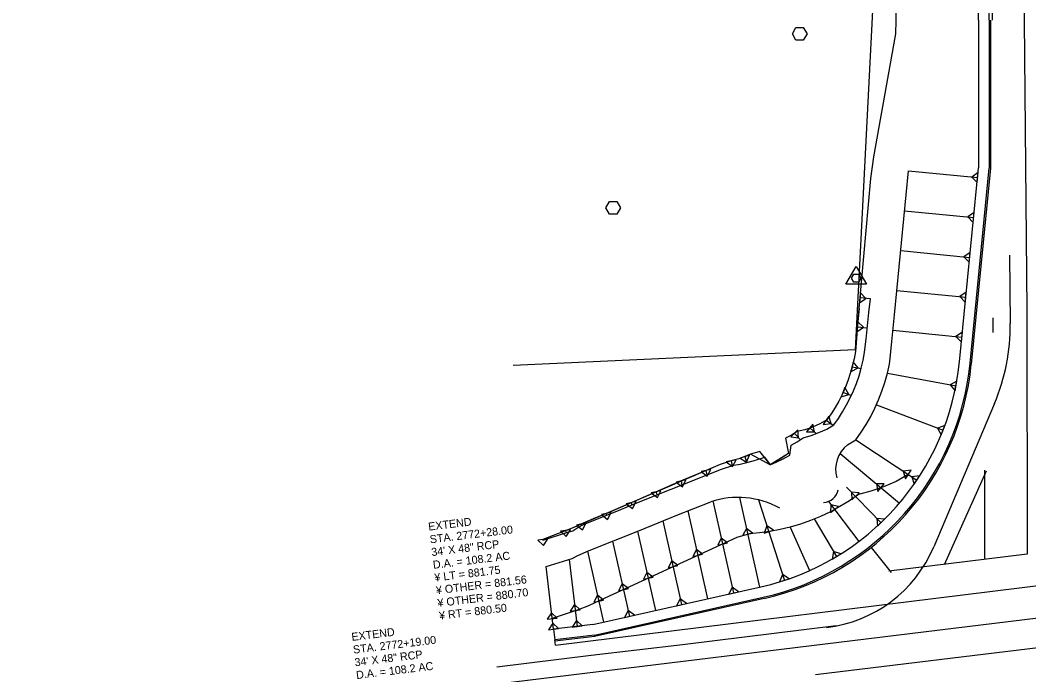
# Model space of a CAD drawing. Extents: x 18436148 to 18440034, y 7649939 to 7652226.
# Drawn here: x 18437956.9 to 18438334.9, y 7650259.9 to 7650505.1 of the extents above; entities that cross this region are included whole.
import ezdxf

# ---------------------------------------------------------------- set-up
doc = ezdxf.new("R2010")
doc.units = 0
for name, color, linetype in [('ATVEHICLE', 7, 'Continuous'), ('Drainage', 7, 'Continuous'), ('ROWTitleBlock', 7, 'Continuous'), ('Seeding', 7, 'Continuous'), ('TC_PCCPavement', 7, 'Continuous'), ('TC_Subbase', 7, 'Continuous'), ('TL_DitchFront', 7, 'Continuous'), ('TL_ShoulderBtm', 7, 'Continuous'), ('TSDETAILS', 7, 'Continuous'), ('TSOUTLINE', 7, 'Continuous')]:
    doc.layers.add(name, color=color, linetype=linetype)

msp = doc.modelspace()

# ---------------------------------------------------------------- linework, layer by layer
at = {"layer": 'ATVEHICLE'}
for p, q in [((18438320.05, 7650505.03), (18438320.13, 7650449.63)), ((18438312.93, 7650376.67), (18438320.13, 7650449.63)), ((18438157.51, 7650270.99), (18438464.57, 7650308.82)), ((18438172.17, 7650274.74), (18438235.33, 7650288.92)), ((18438403.52, 7650277.97), (18438255.05, 7650259.88)), ((18438172.17, 7650274.74), (18438157.28, 7650272.98)), ((18438157.51, 7650270.99), (18438157.28, 7650272.98))]:
    msp.add_line(p, q, dxfattribs=at)
for centre, radius, start, end in [((18431834.06, 7650496.24), 6486, 0.077652, 3.256258), ((18438213.41, 7650386.49), 100, 282.6576, 354.3671)]:
    msp.add_arc(centre, radius, start, end, dxfattribs=at)
at = {"layer": 'Drainage'}
for p, q in [((18438246.31, 7650499.94), (18438247.68, 7650502.32)), ((18438247.68, 7650502.32), (18438250.43, 7650502.32)), ((18438250.43, 7650502.32), (18438251.81, 7650499.94)), ((18438247.68, 7650497.56), (18438246.31, 7650499.94)), ((18438251.81, 7650499.94), (18438250.43, 7650497.56)), ((18438250.43, 7650497.56), (18438247.68, 7650497.56)), ((18438176.4, 7650434.84), (18438177.77, 7650437.22)), ((18438177.77, 7650432.46), (18438176.4, 7650434.84)), ((18438177.77, 7650437.22), (18438180.52, 7650437.22)), ((18438180.52, 7650437.22), (18438181.9, 7650434.84)), ((18438181.9, 7650434.84), (18438180.52, 7650432.46)), ((18438180.52, 7650432.46), (18438177.77, 7650432.46))]:
    msp.add_line(p, q, dxfattribs=at)
at = {"layer": 'Seeding'}
for p, q in [((18438266.31, 7650406.17), (18438270.18, 7650412.88)), ((18438270.18, 7650412.88), (18438274.06, 7650406.17)), ((18438268.43, 7650408.41), (18438269.31, 7650409.93)), ((18438269.31, 7650406.89), (18438268.43, 7650408.41)), ((18438269.31, 7650409.93), (18438271.06, 7650409.93)), ((18438271.06, 7650409.93), (18438271.93, 7650408.41)), ((18438271.93, 7650408.41), (18438271.06, 7650406.89)), ((18438274.06, 7650406.17), (18438266.31, 7650406.17)), ((18438271.06, 7650406.89), (18438269.31, 7650406.89))]:
    msp.add_line(p, q, dxfattribs=at)
at = {"layer": 'TC_PCCPavement'}
for p, q in [((18438282.29, 7650624.06), (18438269.8, 7650381.63)), ((18438269.8, 7650381.63), (18438141.66, 7650375.79))]:
    msp.add_line(p, q, dxfattribs=at)
at = {"layer": 'TC_Subbase'}
for p, q in [((18438289.86, 7650448.66), (18438315.78, 7650446.11)), ((18438288.4, 7650433.73), (18438314.31, 7650431.18)), ((18438286.93, 7650418.8), (18438312.83, 7650416.25)), ((18438285.47, 7650403.88), (18438311.36, 7650401.32)), ((18438275.54, 7650400.67), (18438271.66, 7650401.06)), ((18438270.73, 7650390.26), (18438274.38, 7650389.9)), ((18438284.01, 7650388.95), (18438309.89, 7650386.39)), ((18438268.74, 7650375.28), (18438272.12, 7650374.66)), ((18438281.97, 7650372.85), (18438307.65, 7650368.12)), ((18438265.45, 7650365.64), (18438268.44, 7650364.51)), ((18438277.79, 7650360.96), (18438302.8, 7650351.48)), ((18438258.95, 7650355.23), (18438261.65, 7650353.44)), ((18438252.84, 7650352.34), (18438255.4, 7650350.19)), ((18438247.07, 7650350.31), (18438249.38, 7650347.93)), ((18438270.08, 7650347.89), (18438292.99, 7650332.79)), ((18438223.38, 7650340.04), (18438223.81, 7650338.15)), ((18438228.51, 7650341.64), (18438229.17, 7650339.56)), ((18438264.21, 7650342.81), (18438286.43, 7650324.2)), ((18438213.95, 7650336.42), (18438214.32, 7650334.78)), ((18438204.6, 7650332.45), (18438204.91, 7650331.04)), ((18438195.25, 7650328.43), (18438195.51, 7650327.27)), ((18438266.66, 7650330.13), (18438279.52, 7650316.88)), ((18438185.92, 7650324.35), (18438186.11, 7650323.5)), ((18438216.52, 7650325.01), (18438224.31, 7650290.54)), ((18438226.47, 7650326.35), (18438234.06, 7650292.74)), ((18438233.69, 7650325.41), (18438243.31, 7650295.26)), ((18438259.87, 7650324.82), (18438271.19, 7650309.82)), ((18438176.58, 7650320.29), (18438176.72, 7650319.71)), ((18438207.12, 7650321.26), (18438214.55, 7650288.35)), ((18438197.72, 7650317.5), (18438204.79, 7650286.16)), ((18438254.55, 7650318.26), (18438262.84, 7650304.19)), ((18438161.33, 7650313.93), (18438161.4, 7650313.27)), ((18438167.22, 7650316.38), (18438167.33, 7650315.86)), ((18438188.32, 7650313.73), (18438195.04, 7650283.97)), ((18438245.44, 7650315.19), (18438252.79, 7650298.94)), ((18438178.92, 7650309.94), (18438185.28, 7650281.78)), ((18438169.53, 7650306.15), (18438175.52, 7650279.59)), ((18438162.63, 7650303.05), (18438165.63, 7650277.99)), ((18438156.81, 7650276.95), (18438154.03, 7650300.41))]:
    msp.add_line(p, q, dxfattribs=at)
for points in [[(18438267.01, 7650346.03), (18438270.08, 7650347.89), (18438272.1, 7650350.74), (18438273.96, 7650353.64), (18438275.67, 7650356.63), (18438277.24, 7650359.72), (18438278.65, 7650362.89), (18438279.91, 7650366.13), (18438281.02, 7650369.43), (18438281.97, 7650372.85), (18438282.66, 7650376.23), (18438283.08, 7650379.62), (18438283.58, 7650384.71), (18438284.08, 7650389.69), (18438284.56, 7650394.66), (18438289.86, 7650448.66)], [(18438240.48, 7650339.61), (18438242.92, 7650340.82), (18438245.31, 7650342.16), (18438245.85, 7650345.85), (18438248.18, 7650347.14), (18438250.41, 7650348.61), (18438253.35, 7650349.49), (18438256.28, 7650350.59), (18438259.19, 7650351.9), (18438261.84, 7650353.56), (18438263.56, 7650355.94), (18438265.17, 7650358.41), (18438266.65, 7650360.96), (18438268.02, 7650363.59), (18438269.25, 7650366.29), (18438270.35, 7650369.05), (18438271.32, 7650371.88), (18438272.15, 7650374.76), (18438272.84, 7650377.68), (18438273.37, 7650380.57), (18438273.38, 7650380.69), (18438273.92, 7650385.66), (18438274.46, 7650390.63), (18438274.99, 7650395.61), (18438275.54, 7650400.67)], [(18438271.3, 7650397.13), (18438270.77, 7650391), (18438270.35, 7650386.02), (18438269.93, 7650381.03), (18438269.92, 7650380.92), (18438269.42, 7650378.19), (18438268.78, 7650375.43), (18438268, 7650372.72), (18438267.11, 7650370.05), (18438266.09, 7650367.43), (18438264.95, 7650364.87), (18438263.68, 7650362.38), (18438262.3, 7650359.97), (18438260.8, 7650357.63), (18438259.18, 7650355.37), (18438256.63, 7650353.83), (18438253.81, 7650352.66), (18438250.97, 7650351.7), (18438248.12, 7650350.96), (18438245.99, 7650349.62), (18438243.77, 7650348.46), (18438244.81, 7650342.84), (18438242.61, 7650341.3), (18438240.32, 7650339.89), (18438237.96, 7650338.61), (18438234.15, 7650343.58), (18438230.64, 7650342.54), (18438228.46, 7650341.62), (18438226.23, 7650340.83), (18438223.81, 7650340.19), (18438219.3, 7650338.7), (18438214.62, 7650336.71), (18438205.27, 7650332.73), (18438200.59, 7650330.74), (18438195.92, 7650328.72), (18438191.25, 7650326.7), (18438181.92, 7650322.59), (18438177.25, 7650320.57), (18438172.57, 7650318.62), (18438167.88, 7650316.68), (18438163.84, 7650314.83), (18438152.83, 7650310.58)], [(18438152.86, 7650310.34), (18438162.57, 7650313.38), (18438164.04, 7650313.84), (18438165.9, 7650315.07), (18438167.99, 7650316.17), (18438172.69, 7650318.07), (18438177.39, 7650319.96), (18438182.09, 7650321.86), (18438186.79, 7650323.75), (18438191.49, 7650325.64), (18438196.19, 7650327.52), (18438200.89, 7650329.4), (18438205.59, 7650331.28), (18438210.3, 7650333.16), (18438215, 7650335.03), (18438219.71, 7650336.9), (18438224.36, 7650338.36), (18438226.8, 7650338.8), (18438229.22, 7650339.38), (18438231.6, 7650340.09), (18438234.94, 7650341.07), (18438235.85, 7650341.36), (18438237.99, 7650338.53), (18438240.48, 7650339.61)], [(18438289.76, 7650334.92), (18438285.22, 7650332.23), (18438280.5, 7650330.31), (18438275.77, 7650328.73), (18438271.06, 7650327.47), (18438267.71, 7650325.04), (18438264.17, 7650322.9), (18438260.56, 7650320.96), (18438256.88, 7650319.22), (18438253.14, 7650317.68), (18438249.37, 7650316.35), (18438245.55, 7650315.22), (18438241.72, 7650314.29), (18438237.87, 7650313.57), (18438234.03, 7650313.05), (18438230.25, 7650312.75), (18438225.46, 7650311.3), (18438174.36, 7650287.8), (18438169.89, 7650285.7), (18438166.02, 7650284.21), (18438156.34, 7650280.92)], [(18438154.03, 7650300.41), (18438163.75, 7650303.39), (18438165.97, 7650304.59), (18438170.18, 7650306.41), (18438188.98, 7650313.99), (18438203.08, 7650319.65), (18438215.74, 7650324.7)]]:
    msp.add_lwpolyline(points, dxfattribs=at)
for points in [[(18438313.52, 7650446.33), (18438315.57, 7650444.24), (18438315.95, 7650447.97)], [(18438312.05, 7650431.41), (18438314.1, 7650429.31), (18438314.48, 7650433.04)], [(18438310.58, 7650416.48), (18438312.62, 7650414.38), (18438313.01, 7650418.11)], [(18438273.9, 7650400.83), (18438271.84, 7650402.92), (18438271.47, 7650399.19)], [(18438309.09, 7650401.55), (18438311.13, 7650399.46), (18438311.51, 7650403.19)], [(18438272.95, 7650390.04), (18438270.89, 7650392.13), (18438270.53, 7650388.39)], [(18438307.63, 7650386.61), (18438309.69, 7650384.53), (18438310.05, 7650388.26)], [(18438270.95, 7650374.87), (18438269.08, 7650377.12), (18438268.4, 7650373.44)], [(18438305.42, 7650368.49), (18438307.29, 7650366.23), (18438307.97, 7650369.92)], [(18438267.42, 7650364.89), (18438265.98, 7650367.45), (18438264.65, 7650363.94)], [(18438260.83, 7650353.99), (18438259.98, 7650356.79), (18438257.92, 7650353.66)], [(18438248.65, 7650348.69), (18438248.42, 7650351.61), (18438245.73, 7650349)], [(18438254.57, 7650350.89), (18438254.05, 7650353.77), (18438251.64, 7650350.9)], [(18438300.7, 7650352.28), (18438302.14, 7650349.73), (18438303.47, 7650353.23)], [(18438223.88, 7650337.85), (18438225.21, 7650340.46), (18438221.55, 7650339.63)], [(18438229.19, 7650339.5), (18438230.3, 7650342.21), (18438226.72, 7650341.07)], [(18438214.44, 7650334.23), (18438215.77, 7650336.84), (18438212.12, 7650336.01)], [(18438287.89, 7650336.16), (18438288.73, 7650333.35), (18438290.8, 7650336.49)], [(18438205.09, 7650330.25), (18438206.42, 7650332.86), (18438202.77, 7650332.03)], [(18438291.11, 7650334.03), (18438291.96, 7650331.23), (18438294.02, 7650334.36)], [(18438195.75, 7650326.24), (18438197.08, 7650328.84), (18438193.42, 7650328.02)], [(18438268.43, 7650328.31), (18438268.64, 7650325.39), (18438271.34, 7650328)], [(18438277.8, 7650331.43), (18438278.32, 7650328.55), (18438280.73, 7650331.42)], [(18438186.41, 7650322.16), (18438187.75, 7650324.76), (18438184.09, 7650323.94)], [(18438177.08, 7650318.1), (18438178.41, 7650320.7), (18438174.76, 7650319.88)], [(18438260.79, 7650323.61), (18438260.65, 7650320.68), (18438263.64, 7650322.94)], [(18438167.71, 7650314.19), (18438169.04, 7650316.79), (18438165.39, 7650315.97)], [(18438277.96, 7650318.49), (18438278.18, 7650315.57), (18438280.87, 7650318.18)], [(18438161.59, 7650311.7), (18438163.19, 7650314.15), (18438159.46, 7650313.71)], [(18438229.09, 7650314.74), (18438227.76, 7650312.14), (18438231.42, 7650312.96)], [(18438236.8, 7650315.66), (18438235.7, 7650312.95), (18438239.27, 7650314.09)], [(18438153.1, 7650308.34), (18438154.69, 7650310.8), (18438150.97, 7650310.35)], [(18438219.67, 7650311.07), (18438218.33, 7650308.47), (18438221.99, 7650309.29)], [(18438210.38, 7650306.82), (18438209.05, 7650304.21), (18438212.7, 7650305.03)], [(18438261.7, 7650306.13), (18438261.22, 7650303.24), (18438264.45, 7650305.14)], [(18438201.09, 7650302.56), (18438199.76, 7650299.95), (18438203.41, 7650300.77)], [(18438191.81, 7650298.26), (18438190.47, 7650295.66), (18438194.13, 7650296.48)], [(18438182.53, 7650293.97), (18438181.19, 7650291.36), (18438184.85, 7650292.19)], [(18438242.62, 7650297.41), (18438241.52, 7650294.69), (18438245.09, 7650295.83)], [(18438223.81, 7650292.74), (18438222.47, 7650290.13), (18438226.13, 7650290.95)], [(18438173.25, 7650289.68), (18438171.91, 7650287.07), (18438175.57, 7650287.89)], [(18438204.3, 7650288.36), (18438202.96, 7650285.75), (18438206.62, 7650286.57)], [(18438156.07, 7650283.15), (18438154.47, 7650280.7), (18438158.2, 7650281.14)], [(18438164.65, 7650286.18), (18438163.05, 7650283.73), (18438166.78, 7650284.17)], [(18438184.78, 7650283.97), (18438183.45, 7650281.37), (18438187.11, 7650282.19)], [(18438156.54, 7650279.18), (18438154.94, 7650276.73), (18438158.67, 7650277.17)], [(18438165.36, 7650280.22), (18438163.76, 7650277.77), (18438167.49, 7650278.21)]]:
    msp.add_lwpolyline(points, close=True, dxfattribs=at)
for centre, radius, start, end in [((18438274.44, 7650336.73), 11.91, 128.6043, 194.8147), ((18438257.72, 7650330.28), 5.86, 273.0563, 349.5073), ((18438225.93, 7650294.24), 32.11, 60.8541, 108.5006)]:
    msp.add_arc(centre, radius, start, end, dxfattribs=at)
at = {"layer": 'TL_DitchFront'}
for p, q in [((18438327.75, 7650417.02), (18438328, 7650391.45)), ((18438322.06, 7650361.48), (18438299.31, 7650307.78))]:
    msp.add_line(p, q, dxfattribs=at)
msp.add_lwpolyline([(18438262.79, 7650278.2), (18438205.17, 7650271.07), (18438170.88, 7650267.09), (18438135.62, 7650262.7)], dxfattribs=at)
for centre, radius, start, end in [((18438253, 7650390.74), 75, 337.0435, 0.5467), ((18438253.27, 7650327.28), 50, 276.6667, 337.0435)]:
    msp.add_arc(centre, radius, start, end, dxfattribs=at)
at = {"layer": 'TL_ShoulderBtm'}
for p, q in [((18438320.55, 7650505.03), (18438320.63, 7650449.63)), ((18438320.63, 7650449.63), (18438313.39, 7650376.26)), ((18438334.2, 7650396.45), (18438334.32, 7650305.07)), ((18438321.54, 7650388.15), (18438321.53, 7650393.57)), ((18438303.33, 7650301.24), (18438319.08, 7650336.3)), ((18438318.28, 7650336.54), (18438318.33, 7650303.09)), ((18438275.89, 7650307.63), (18438283.33, 7650298.22)), ((18438530.78, 7650304.56), (18436148.4, 7650014.28)), ((18438334.32, 7650305.07), (18438282.46, 7650298.66)), ((18438235.79, 7650288.51), (18438172.13, 7650274.21)), ((18438172.28, 7650274.25), (18438157.33, 7650272.48))]:
    msp.add_line(p, q, dxfattribs=at)
msp.add_lwpolyline([(18438321.58, 7650902.32), (18438328.02, 7650754.94), (18438328.39, 7650745.35), (18438328.96, 7650729.96), (18438329.82, 7650704.97), (18438330.42, 7650685.28), (18438331.23, 7650654.99), (18438331.89, 7650625.2), (18438332.26, 7650605), (18438332.8, 7650565.11), (18438332.9, 7650555.01), (18438333.16, 7650505.01), (18438334.2, 7650396.45)], dxfattribs=at)
for centre, radius, start, end in [((18431834.89, 7650496.24), 6486.5, 0.077652, 3.256258), ((18438213.87, 7650386.08), 100, 282.6576, 354.3671)]:
    msp.add_arc(centre, radius, start, end, dxfattribs=at)
at = {"layer": 'TSDETAILS'}
for p, q in [((18438316.05, 7650505.03), (18438316.13, 7650449.83)), ((18438308.95, 7650377.07), (18438316.13, 7650449.83)), ((18438171.5, 7650278.68), (18438234.45, 7650292.82)), ((18438171.5, 7650278.68), (18438156.81, 7650276.95)), ((18438171.5, 7650278.68), (18438156.81, 7650276.95)), ((18438156.81, 7650276.95), (18438157.28, 7650272.98))]:
    msp.add_line(p, q, dxfattribs=at)
for centre, radius, start, end in [((18431834.06, 7650496.24), 6482, 0.077652, 3.256258), ((18438213.41, 7650386.49), 96, 282.6576, 354.3671)]:
    msp.add_arc(centre, radius, start, end, dxfattribs=at)
at = {"layer": 'TSOUTLINE'}
for points in [[(18438271.3, 7650397.13), (18438275.78, 7650445.77), (18438276.79, 7650453.91), (18438285.13, 7650499.99), (18438285.26, 7650504.99), (18438286.16, 7650554.62)], [(18438271.29, 7650397.09), (18438269.92, 7650380.92), (18438269.42, 7650378.19), (18438268.78, 7650375.43), (18438268, 7650372.72), (18438267.11, 7650370.05), (18438266.09, 7650367.43), (18438264.95, 7650364.87), (18438263.68, 7650362.38), (18438262.3, 7650359.97), (18438260.8, 7650357.63), (18438259.18, 7650355.37), (18438256.63, 7650353.83), (18438253.81, 7650352.66), (18438250.97, 7650351.7), (18438248.12, 7650350.96), (18438245.99, 7650349.62), (18438243.77, 7650348.46), (18438244.81, 7650342.84), (18438237.99, 7650338.53), (18438230.64, 7650342.54), (18438226.23, 7650340.83), (18438223.81, 7650340.19), (18438219.3, 7650338.7), (18438163.84, 7650314.83), (18438152.83, 7650310.58)]]:
    msp.add_lwpolyline(points, dxfattribs=at)

# ---------------------------------------------------------------- texts
at = {"layer": 'ROWTitleBlock'}
for s, p in [('EXTEND', (18438110.05, 7650313.87)), ('STA. 2772+28.00', (18438110.63, 7650309.11)), ('34\' X 48" RCP', (18438111.21, 7650304.34)), ('D.A. = 108.2 AC', (18438111.8, 7650299.58)), ('¥ LT = 881.75', (18438112.38, 7650294.81)), ('¥ OTHER = 881.56', (18438112.96, 7650290.05)), ('¥ OTHER = 880.70', (18438113.54, 7650285.28)), ('¥ RT = 880.50', (18438114.12, 7650280.52)), ('EXTEND', (18438081.28, 7650272.57)), ('STA. 2772+19.00', (18438081.86, 7650267.8)), ('34\' X 48" RCP', (18438082.44, 7650263.04)), ('D.A. = 108.2 AC', (18438083.02, 7650258.27))]:
    msp.add_text(s, height=3, rotation=6.947, dxfattribs=at).set_placement(p)

doc.saveas('drawing.dxf')
